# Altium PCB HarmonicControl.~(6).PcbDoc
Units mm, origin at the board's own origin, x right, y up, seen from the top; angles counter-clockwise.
Board outline 133.86 x 40.01 mm, 2 copper layers (Top Layer, Bottom Layer); 10 components, 14 nets, 55 pads, 0 vias.
Unrouted connection lines stored in the file: 17.
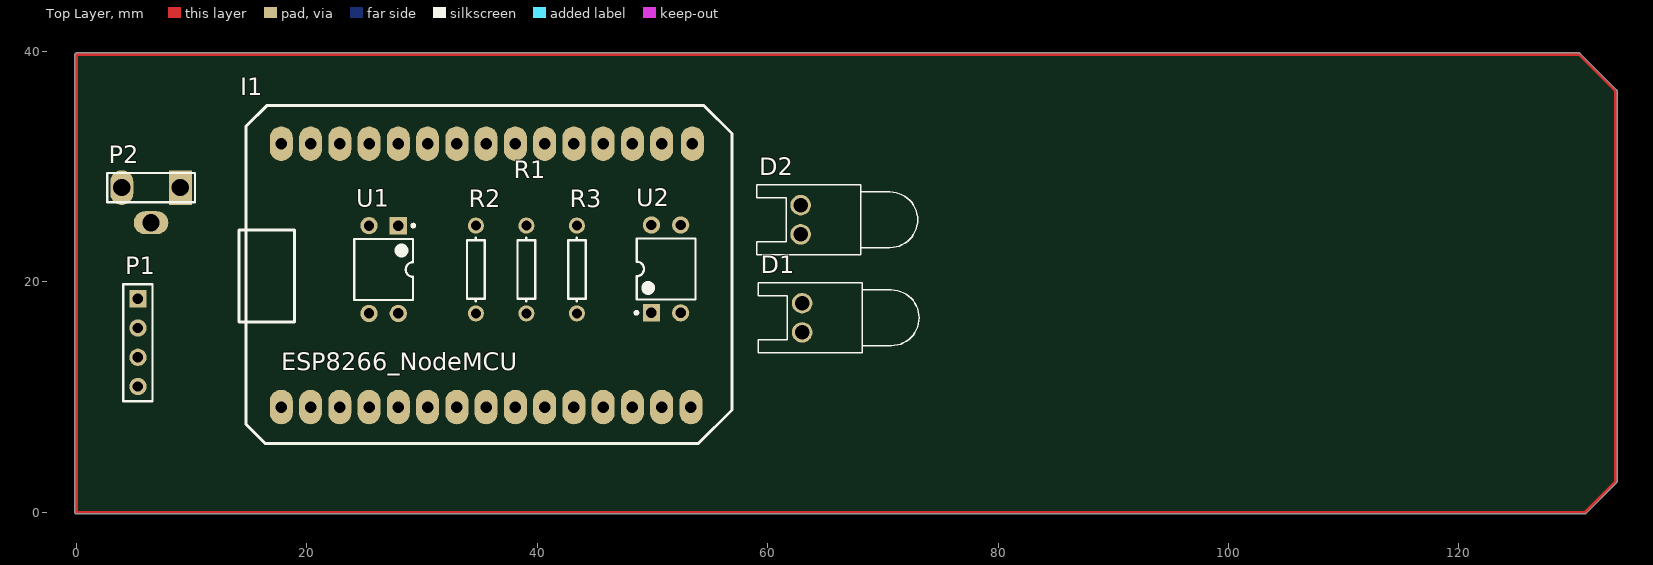
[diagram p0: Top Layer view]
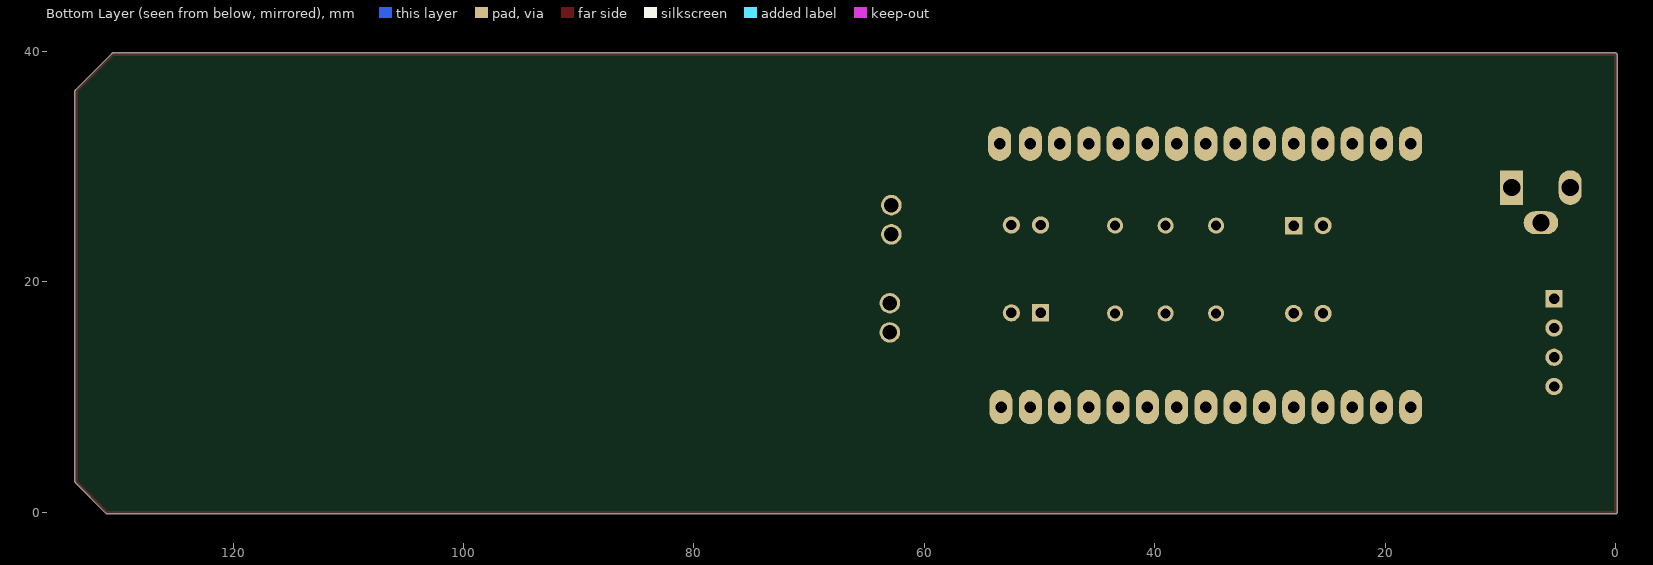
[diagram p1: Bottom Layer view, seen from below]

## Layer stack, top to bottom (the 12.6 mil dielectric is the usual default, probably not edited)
Top Solder: solder mask 0.0102, Solder Resist, Dk 3.5
Top Layer: signal copper 0.0356
Dielectric 1: dielectric 0.32, FR-4, Dk 4.8
Bottom Layer: signal copper 0.0356
Bottom Solder: solder mask 0.0102, Solder Resist, Dk 3.5

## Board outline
0.064,-0.11 cw(c0,0) -0.127,0 -0.127,39.751 cw(c0,39.751) 0,39.878 130.429,39.878 cw(c130.429,39.751) 130.52,39.841 130.519,39.841 133.694,36.666 133.694,36.667 cw(c133.604,36.576) 133.731,36.576 133.731,2.667 cw(c133.604,2.667) 133.694,2.576 133.694,2.577 131.027,-0.09 131.028,-0.09 cw(c130.937,0) 130.937,-0.127 0.127,-0.127 cw(c0.127,0)

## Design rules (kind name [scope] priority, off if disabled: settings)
Clearance [All] p1: gap=0.8 ignorepadtopadclearanceinfootprint=FALSE
PolygonConnect [All] p1: connectstyle=Relief reliefconductorwidth=0.254 reliefentries=4 polygonreliefangle="90 Angle" airgapwidth=0.254
RoutingVias [All] p1: holewidth=0.711 width=1.27 viastyle="Through Hole" minholewidth=0.711 minwidth=1.27 maxholewidth=0.711 maxwidth=1.27
SolderMaskExpansion [All] p1: expansion=0.102
Width [All] p1: maxlimit=1 minlimit=0.5 preferedwidth=0.8
30 further rules are at their usual default settings.

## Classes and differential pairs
component class HarmonicControl: D1 D2 P1 P2 R1 R2 R3 U1 U2

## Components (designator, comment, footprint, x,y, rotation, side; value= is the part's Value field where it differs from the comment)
D1 "LED0" LED-0 62.992,16.891 r90 top
D2 "LED0" LED-0 62.865,25.4 r90 top
I1 "ESP8266" ESP8266_Node_MCU_V3 17.78,32.004 r270 top
P1 "Cable" HDR1X4 5.334,18.542 r270 top
P2 "Jack3.5mm" HDR1X3 9.017,28.194 r180 top
R1 "Res1" AXIAL-0.3 39.056,21.082 r90 top value=1K
R2 "Res1" AXIAL-0.3 34.671,21.082 r270 top value=1K
R3 "Res1" AXIAL-0.3 43.441,21.082 r270 top value=1K
U1 "InputSignal" DIP-4 26.67,21.082 r270 top
U2 "Output_Control" DIP-4 51.181,21.132 r90 top

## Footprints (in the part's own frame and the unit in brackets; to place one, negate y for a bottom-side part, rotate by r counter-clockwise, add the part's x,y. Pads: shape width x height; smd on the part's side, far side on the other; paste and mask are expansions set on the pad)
AXIAL-0.3 [mm] "Axial Device, Thru-Hole; 2 Leads; 0.3 in Pin Spacing"
  round 1.4 hole 0.85: 1(-3.81,0) 2(3.81,0)
  silkscreen extent -2.77,-0.76 2.77,0.76
DIP-4 [mm] "DIP; 4 Leads; Row Spacing 7.62 mm; Pitch 2.54 mm"
  rect 1.5x1.5 hole 0.9: 1(-3.81,1.27)
  round 1.5 hole 0.9: 2(-3.81,-1.27) 3(3.81,-1.27) 4(3.81,1.27)
  silkscreen extent -3.93,-2.55 2.65,2.7, body extent -3.15,-2.5 3.15,2.5, height 5.6
ESP8266_Node_MCU_V3 [mm]
  oval 3x2 hole 1 paste+0 mask+0.102: 1(22.86,35.56) 2(22.86,33.02) 3(22.86,30.48) 4(22.86,27.94) 5(22.86,25.4) 6(22.86,22.86) 7(22.86,20.32) 8(22.86,17.78) 9(22.86,15.24) 10(22.86,12.7) 11(22.86,10.16) 12(22.86,7.62) 13(22.86,5.08) 14(22.86,2.54) 15(22.86,0) 16(0,0) 17(0,2.54) 18(0,5.08) 19(0,7.62) 20(0,10.16) 21(0,12.7) 22(0,15.24) 23(0,17.78) 24(0,20.32) 25(0,22.86) 26(0,25.4) 27(0,27.94) 28(0,30.48) 29(0,33.02) 30(0,35.687)
  silkscreen extent -3.3,-3.68 26.04,39.12
HDR1X3 [mm] "Connector; Header; 3 Position"
  rect 2x3 hole 1.5: 1(0,0)
  oval 3x2 hole 1.5: 2(2.54,3.05)
  oval 2x3 hole 1.5: 3(5.08,0)
  silkscreen extent -1.27,-1.27 6.35,1.27
HDR1X4 [mm] "Connector; Header; 4 Position"
  rect 1.5x1.5 hole 0.9: 1(0,0)
  round 1.5 hole 0.9: 2(2.54,0) 3(5.08,0) 4(7.62,0)
  silkscreen extent -1.27,-1.27 8.89,1.27
LED-0 [mil] "LED; 2 Leads"
  round 70 hole 50: 1(50,0) 2(-50,0)
  silkscreen extent -120,-400 120,150

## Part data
D1 D2: "Typical INFRARED GaAs LED"
I1: library part ESP8266_Node_MCU_V3
P1: library part "Header 4", "Header, 4-Pin"
P2: library part "Header 3", "Header, 3-Pin"
R1 R2 R3: "Resistor"
U1 U2: library part Optoisolator1, "4-Pin Phototransistor Optocoupler"

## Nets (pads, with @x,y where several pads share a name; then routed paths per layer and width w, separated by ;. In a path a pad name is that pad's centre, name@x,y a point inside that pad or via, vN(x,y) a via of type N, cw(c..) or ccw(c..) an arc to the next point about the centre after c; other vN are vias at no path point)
GND: D1.2 I1.17 P2.2 P2.3
NetD1_1: D1.1 R2.2
NetD2_1: D2.1 R3.1
NetD2_2: D2.2 I1.14
NetI1_1: I1.1 R2.1 U1.2
NetI1_3: I1.3 U2.1
NetI1_16: I1.16 P2.1
NetI1_20: I1.20 U1.1
NetP1_1: P1.1 U1.4
NetP1_2: P1.2 R1.2
NetP1_3: P1.3 U2.4
NetP1_4: P1.4 U2.3
NetR1_1: R1.1 U1.3
NetR3_2: R3.2 U2.2
pads on no net: I1.2 I1.4 I1.5 I1.6 I1.7 I1.8 I1.9 I1.10 I1.11 I1.12 I1.13 I1.15 I1.18 I1.19 I1.21 I1.22 I1.23 I1.24 I1.25 I1.26 I1.27 I1.28 I1.29 I1.30
copper on no net: | length 343.2
  Top Layer w0.254: 0,0 0,39.751 130.429,39.751 133.604,36.576 133.604,2.667 130.937,0 0.127,0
